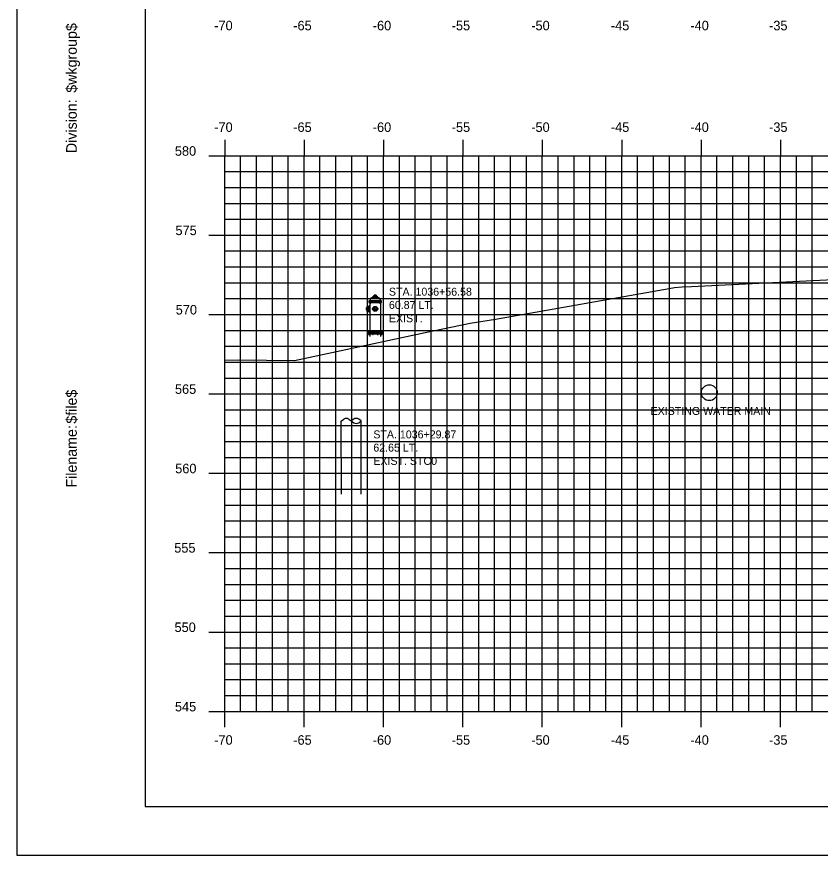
# Model space of a CAD drawing. Extents: x 1060559 to 1060729, y 779716 to 779826.
# Drawn here: x 1060559 to 1060609.6, y 779715.6 to 779768.5 of the extents above; entities that cross this region are included whole.
import ezdxf

# ---------------------------------------------------------------- set-up
doc = ezdxf.new("R2010")
doc.units = 0
for name, color, linetype in [('BORDER', 7, 'Continuous'), ('D_Text_Monospaced', 7, 'Continuous'), ('Existing Water Main', 7, 'Continuous'), ('H_V ANNOTATION', 7, 'Continuous'), ('M_Utilities_Hydrant', 7, 'Continuous'), ('MAJOR', 7, 'Continuous'), ('MINOR', 7, 'Continuous'), ('PLOT BOUNDARY', 7, 'Continuous'), ('S_Roadway_Centerline', 7, 'Continuous'), ('S_Utilities_Hydrant', 7, 'Continuous'), ('S_Utilities_Pole_Joint', 7, 'Continuous'), ('S_Utilities_Pole_Power', 7, 'Continuous')]:
    doc.layers.add(name, color=color, linetype=linetype)

msp = doc.modelspace()

# ---------------------------------------------------------------- linework, layer by layer
at = {"layer": 'BORDER'}
msp.add_lwpolyline([(1060567.08, 779718.706), (1060727.08, 779718.706), (1060727.08, 779823.706), (1060567.08, 779823.706)], close=True, dxfattribs=at)
at = {"layer": 'Existing Water Main'}
msp.add_circle((1060602.596, 779744.78), 0.501, dxfattribs=at)
at = {"layer": 'M_Utilities_Hydrant'}
for p, q in [((1060581.949, 779750.51), (1060581.16, 779750.51)), ((1060581.216, 779750.453), (1060581.216, 779748.647)), ((1060581.235, 779750.566), (1060581.235, 779750.583)), ((1060581.235, 779750.429), (1060581.235, 779750.453)), ((1060581.264, 779750.583), (1060581.264, 779750.566)), ((1060581.264, 779750.453), (1060581.264, 779750.429)), ((1060581.845, 779750.583), (1060581.845, 779750.566)), ((1060581.845, 779750.453), (1060581.845, 779750.429)), ((1060581.873, 779750.566), (1060581.873, 779750.583)), ((1060581.873, 779750.429), (1060581.873, 779750.453)), ((1060581.892, 779750.453), (1060581.892, 779748.647)), ((1060581.013, 779750.104), (1060581.013, 779750.014)), ((1060581.024, 779750.119), (1060581.024, 779749.998)), ((1060581.028, 779750.12), (1060581.028, 779749.998)), ((1060581.125, 779750.233), (1060581.125, 779749.884)), ((1060581.132, 779750.224), (1060581.125, 779750.224)), ((1060581.132, 779749.895), (1060581.125, 779749.895)), ((1060581.132, 779749.89), (1060581.132, 779750.228)), ((1060582.035, 779748.59), (1060581.084, 779748.59)), ((1060582.035, 779748.534), (1060581.084, 779748.534)), ((1060581.144, 779748.664), (1060581.144, 779748.647)), ((1060581.144, 779748.477), (1060581.144, 779748.453)), ((1060581.172, 779748.647), (1060581.172, 779748.664)), ((1060581.172, 779748.453), (1060581.172, 779748.477)), ((1060581.216, 779748.477), (1060581.216, 779748.311)), ((1060581.396, 779748.664), (1060581.396, 779748.647)), ((1060581.396, 779748.477), (1060581.396, 779748.453)), ((1060581.424, 779748.647), (1060581.424, 779748.664)), ((1060581.424, 779748.453), (1060581.424, 779748.477)), ((1060581.696, 779748.664), (1060581.696, 779748.647)), ((1060581.696, 779748.477), (1060581.696, 779748.453)), ((1060581.724, 779748.647), (1060581.724, 779748.664)), ((1060581.724, 779748.453), (1060581.724, 779748.477)), ((1060581.892, 779748.477), (1060581.892, 779748.311)), ((1060581.947, 779748.664), (1060581.947, 779748.647)), ((1060581.947, 779748.477), (1060581.947, 779748.453)), ((1060581.976, 779748.647), (1060581.976, 779748.664)), ((1060581.976, 779748.453), (1060581.976, 779748.477))]:
    msp.add_line(p, q, dxfattribs=at)
for points in [[(1060581.611, 779750.877), (1060581.611, 779750.933), (1060581.498, 779750.933), (1060581.498, 779750.877)], [(1060581.222, 779750.566), (1060581.222, 779750.583), (1060581.225, 779750.587), (1060581.274, 779750.587), (1060581.277, 779750.583), (1060581.277, 779750.566), (1060581.222, 779750.566)], [(1060581.277, 779750.453), (1060581.277, 779750.429), (1060581.274, 779750.425), (1060581.225, 779750.425), (1060581.222, 779750.429), (1060581.222, 779750.453), (1060581.277, 779750.453)], [(1060581.235, 779750.432), (1060581.235, 779750.416), (1060581.264, 779750.416), (1060581.264, 779750.429)], [(1060581.887, 779750.566), (1060581.887, 779750.583), (1060581.883, 779750.587), (1060581.835, 779750.587), (1060581.831, 779750.583), (1060581.831, 779750.566), (1060581.887, 779750.566)], [(1060581.831, 779750.453), (1060581.831, 779750.429), (1060581.835, 779750.425), (1060581.883, 779750.425), (1060581.887, 779750.429), (1060581.887, 779750.453), (1060581.831, 779750.453)], [(1060581.873, 779750.432), (1060581.873, 779750.416), (1060581.845, 779750.416), (1060581.845, 779750.429)], [(1060581.013, 779750.104), (1060580.978, 779750.104), (1060580.978, 779750.014), (1060581.013, 779750.014)], [(1060581.587, 779750.015), (1060581.522, 779750.015), (1060581.503, 779750.076), (1060581.554, 779750.114), (1060581.606, 779750.076), (1060581.587, 779750.015)], [(1060581.186, 779748.647), (1060581.186, 779748.664), (1060581.182, 779748.668), (1060581.134, 779748.668), (1060581.13, 779748.664), (1060581.13, 779748.647), (1060581.186, 779748.647)], [(1060581.13, 779748.477), (1060581.13, 779748.453), (1060581.134, 779748.45), (1060581.182, 779748.45), (1060581.186, 779748.453), (1060581.186, 779748.477), (1060581.13, 779748.477)], [(1060581.172, 779748.456), (1060581.172, 779748.44), (1060581.144, 779748.44), (1060581.144, 779748.453)], [(1060581.438, 779748.647), (1060581.438, 779748.664), (1060581.434, 779748.668), (1060581.385, 779748.668), (1060581.381, 779748.664), (1060581.381, 779748.647), (1060581.438, 779748.647)], [(1060581.381, 779748.477), (1060581.381, 779748.453), (1060581.385, 779748.45), (1060581.434, 779748.45), (1060581.438, 779748.453), (1060581.438, 779748.477), (1060581.381, 779748.477)], [(1060581.424, 779748.456), (1060581.424, 779748.44), (1060581.396, 779748.44), (1060581.396, 779748.453)], [(1060581.738, 779748.647), (1060581.738, 779748.664), (1060581.734, 779748.668), (1060581.686, 779748.668), (1060581.682, 779748.664), (1060581.682, 779748.647), (1060581.738, 779748.647)], [(1060581.682, 779748.477), (1060581.682, 779748.453), (1060581.686, 779748.45), (1060581.734, 779748.45), (1060581.738, 779748.453), (1060581.738, 779748.477), (1060581.682, 779748.477)], [(1060581.724, 779748.456), (1060581.724, 779748.44), (1060581.696, 779748.44), (1060581.696, 779748.453)], [(1060581.989, 779748.647), (1060581.989, 779748.664), (1060581.986, 779748.668), (1060581.937, 779748.668), (1060581.933, 779748.664), (1060581.933, 779748.647), (1060581.989, 779748.647)], [(1060581.933, 779748.477), (1060581.933, 779748.453), (1060581.937, 779748.45), (1060581.986, 779748.45), (1060581.989, 779748.453), (1060581.989, 779748.477), (1060581.933, 779748.477)], [(1060581.976, 779748.456), (1060581.976, 779748.44), (1060581.947, 779748.44), (1060581.947, 779748.453)]]:
    msp.add_lwpolyline(points, dxfattribs=at)
for radius in [0.158, 0.128]:
    msp.add_circle((1060581.554, 779750.059), radius, dxfattribs=at)
at = {"layer": 'MAJOR'}
for p, q in [((1060572.079, 779760.708), (1060572.079, 779759.706)), ((1060577.079, 779760.708), (1060577.079, 779759.706)), ((1060582.079, 779760.708), (1060582.079, 779759.706)), ((1060587.079, 779760.708), (1060587.079, 779759.706)), ((1060592.079, 779760.708), (1060592.079, 779759.706)), ((1060597.079, 779760.708), (1060597.079, 779759.706)), ((1060602.079, 779760.708), (1060602.079, 779759.706)), ((1060607.079, 779760.708), (1060607.079, 779759.706)), ((1060571.077, 779759.706), (1060572.079, 779759.706)), ((1060572.079, 779759.706), (1060712.079, 779759.706)), ((1060572.079, 779724.706), (1060572.079, 779759.706)), ((1060572.079, 779724.706), (1060572.079, 779759.706)), ((1060572.079, 779759.706), (1060712.079, 779759.706)), ((1060577.079, 779724.706), (1060577.079, 779759.706)), ((1060582.079, 779724.706), (1060582.079, 779759.706)), ((1060587.079, 779724.706), (1060587.079, 779759.706)), ((1060592.079, 779724.706), (1060592.079, 779759.706)), ((1060597.079, 779724.706), (1060597.079, 779759.706)), ((1060602.079, 779724.706), (1060602.079, 779759.706)), ((1060607.079, 779724.706), (1060607.079, 779759.706)), ((1060571.077, 779754.706), (1060572.079, 779754.706)), ((1060572.079, 779754.706), (1060712.079, 779754.706)), ((1060571.077, 779749.706), (1060572.079, 779749.706)), ((1060572.079, 779749.706), (1060712.079, 779749.706)), ((1060571.077, 779744.706), (1060572.079, 779744.706)), ((1060572.079, 779744.706), (1060712.079, 779744.706)), ((1060571.077, 779739.706), (1060572.079, 779739.706)), ((1060572.079, 779739.706), (1060712.079, 779739.706)), ((1060571.077, 779734.706), (1060572.079, 779734.706)), ((1060572.079, 779734.706), (1060712.079, 779734.706)), ((1060571.077, 779729.706), (1060572.079, 779729.706)), ((1060572.079, 779729.706), (1060712.079, 779729.706)), ((1060571.077, 779724.706), (1060572.079, 779724.706)), ((1060572.079, 779724.706), (1060712.079, 779724.706)), ((1060572.079, 779724.706), (1060712.079, 779724.706)), ((1060572.079, 779723.704), (1060572.079, 779724.706)), ((1060577.079, 779723.704), (1060577.079, 779724.706)), ((1060582.079, 779723.704), (1060582.079, 779724.706)), ((1060587.079, 779723.704), (1060587.079, 779724.706)), ((1060592.079, 779723.704), (1060592.079, 779724.706)), ((1060597.079, 779723.704), (1060597.079, 779724.706)), ((1060602.079, 779723.704), (1060602.079, 779724.706)), ((1060607.079, 779723.704), (1060607.079, 779724.706))]:
    msp.add_line(p, q, dxfattribs=at)
at = {"layer": 'MINOR'}
for p, q in [((1060573.079, 779724.706), (1060573.079, 779759.706)), ((1060574.079, 779724.706), (1060574.079, 779759.706)), ((1060575.079, 779724.706), (1060575.079, 779759.706)), ((1060576.079, 779724.706), (1060576.079, 779759.706)), ((1060578.079, 779724.706), (1060578.079, 779759.706)), ((1060579.079, 779724.706), (1060579.079, 779759.706)), ((1060580.079, 779724.706), (1060580.079, 779759.706)), ((1060581.079, 779724.706), (1060581.079, 779759.706)), ((1060583.079, 779724.706), (1060583.079, 779759.706)), ((1060584.079, 779724.706), (1060584.079, 779759.706)), ((1060585.079, 779724.706), (1060585.079, 779759.706)), ((1060586.079, 779724.706), (1060586.079, 779759.706)), ((1060588.079, 779724.706), (1060588.079, 779759.706)), ((1060589.079, 779724.706), (1060589.079, 779759.706)), ((1060590.079, 779724.706), (1060590.079, 779759.706)), ((1060591.079, 779724.706), (1060591.079, 779759.706)), ((1060593.079, 779724.706), (1060593.079, 779759.706)), ((1060594.079, 779724.706), (1060594.079, 779759.706)), ((1060595.079, 779724.706), (1060595.079, 779759.706)), ((1060596.079, 779724.706), (1060596.079, 779759.706)), ((1060598.079, 779724.706), (1060598.079, 779759.706)), ((1060599.079, 779724.706), (1060599.079, 779759.706)), ((1060600.079, 779724.706), (1060600.079, 779759.706)), ((1060601.079, 779724.706), (1060601.079, 779759.706)), ((1060603.079, 779724.706), (1060603.079, 779759.706)), ((1060604.079, 779724.706), (1060604.079, 779759.706)), ((1060605.079, 779724.706), (1060605.079, 779759.706)), ((1060606.079, 779724.706), (1060606.079, 779759.706)), ((1060608.079, 779724.706), (1060608.079, 779759.706)), ((1060609.079, 779724.706), (1060609.079, 779759.706)), ((1060572.079, 779758.706), (1060712.079, 779758.706)), ((1060572.079, 779758.706), (1060573.081, 779758.706)), ((1060572.079, 779757.706), (1060712.079, 779757.706)), ((1060572.079, 779757.706), (1060573.081, 779757.706)), ((1060572.079, 779756.706), (1060712.079, 779756.706)), ((1060572.079, 779756.706), (1060573.081, 779756.706)), ((1060572.079, 779755.706), (1060712.079, 779755.706)), ((1060572.079, 779755.706), (1060573.081, 779755.706)), ((1060572.079, 779753.706), (1060712.079, 779753.706)), ((1060572.079, 779753.706), (1060573.081, 779753.706)), ((1060572.079, 779752.706), (1060712.079, 779752.706)), ((1060572.079, 779752.706), (1060573.081, 779752.706)), ((1060572.079, 779751.706), (1060712.079, 779751.706)), ((1060572.079, 779751.706), (1060573.081, 779751.706)), ((1060572.079, 779750.706), (1060712.079, 779750.706)), ((1060572.079, 779750.706), (1060573.081, 779750.706)), ((1060572.079, 779748.706), (1060712.079, 779748.706)), ((1060572.079, 779748.706), (1060573.081, 779748.706)), ((1060572.079, 779747.706), (1060712.079, 779747.706)), ((1060572.079, 779747.706), (1060573.081, 779747.706)), ((1060572.079, 779746.706), (1060712.079, 779746.706)), ((1060572.079, 779746.706), (1060573.081, 779746.706)), ((1060572.079, 779745.706), (1060712.079, 779745.706)), ((1060572.079, 779745.706), (1060573.081, 779745.706)), ((1060572.079, 779743.706), (1060712.079, 779743.706)), ((1060572.079, 779743.706), (1060573.081, 779743.706)), ((1060572.079, 779742.706), (1060712.079, 779742.706)), ((1060572.079, 779742.706), (1060573.081, 779742.706)), ((1060572.079, 779741.706), (1060712.079, 779741.706)), ((1060572.079, 779741.706), (1060573.081, 779741.706)), ((1060572.079, 779740.706), (1060712.079, 779740.706)), ((1060572.079, 779740.706), (1060573.081, 779740.706)), ((1060572.079, 779738.706), (1060712.079, 779738.706)), ((1060572.079, 779738.706), (1060573.081, 779738.706)), ((1060572.079, 779737.706), (1060712.079, 779737.706)), ((1060572.079, 779737.706), (1060573.081, 779737.706)), ((1060572.079, 779736.706), (1060712.079, 779736.706)), ((1060572.079, 779736.706), (1060573.081, 779736.706)), ((1060572.079, 779735.706), (1060712.079, 779735.706)), ((1060572.079, 779735.706), (1060573.081, 779735.706)), ((1060572.079, 779733.706), (1060712.079, 779733.706)), ((1060572.079, 779733.706), (1060573.081, 779733.706)), ((1060572.079, 779732.706), (1060712.079, 779732.706)), ((1060572.079, 779732.706), (1060573.081, 779732.706)), ((1060572.079, 779731.706), (1060712.079, 779731.706)), ((1060572.079, 779731.706), (1060573.081, 779731.706)), ((1060572.079, 779730.706), (1060712.079, 779730.706)), ((1060572.079, 779730.706), (1060573.081, 779730.706)), ((1060572.079, 779728.706), (1060712.079, 779728.706)), ((1060572.079, 779728.706), (1060573.081, 779728.706)), ((1060572.079, 779727.706), (1060712.079, 779727.706)), ((1060572.079, 779727.706), (1060573.081, 779727.706)), ((1060572.079, 779726.706), (1060712.079, 779726.706)), ((1060572.079, 779726.706), (1060573.081, 779726.706)), ((1060572.079, 779725.706), (1060712.079, 779725.706)), ((1060572.079, 779725.706), (1060573.081, 779725.706))]:
    msp.add_line(p, q, dxfattribs=at)
at = {"layer": 'PLOT BOUNDARY'}
msp.add_lwpolyline([(1060558.986, 779715.646), (1060728.986, 779715.646), (1060728.986, 779825.646), (1060558.986, 779825.646)], close=True, dxfattribs=at)
at = {"layer": 'S_Roadway_Centerline'}
msp.add_lwpolyline([(1060572.079, 779746.823), (1060572.953, 779746.846), (1060576.475, 779746.799), (1060584.699, 779748.564), (1060587.544, 779749.165), (1060589.137, 779749.419), (1060600.06, 779751.353), (1060600.399, 779751.407), (1060600.894, 779751.457), (1060601.472, 779751.475), (1060617.199, 779752.241)], dxfattribs=at)
at = {"layer": 'S_Utilities_Hydrant'}
for p, q in [((1060581.401, 779750.821), (1060581.707, 779750.821)), ((1060581.441, 779750.862), (1060581.441, 779750.821)), ((1060581.65, 779750.878), (1060581.458, 779750.877)), ((1060581.667, 779750.821), (1060581.667, 779750.862)), ((1060581.16, 779750.55), (1060581.16, 779750.469)), ((1060581.932, 779750.566), (1060581.176, 779750.566)), ((1060581.255, 779750.694), (1060581.216, 779750.566)), ((1060581.216, 779750.295), (1060581.216, 779750.295)), ((1060581.554, 779750.765), (1060581.323, 779750.765)), ((1060581.554, 779750.765), (1060581.785, 779750.765)), ((1060581.854, 779750.694), (1060581.892, 779750.566)), ((1060581.013, 779750.107), (1060581.013, 779750.104)), ((1060581.013, 779750.012), (1060581.013, 779750.014)), ((1060581.048, 779750.126), (1060581.04, 779750.125)), ((1060581.048, 779749.991), (1060581.04, 779749.993)), ((1060581.048, 779749.901), (1060581.048, 779750.218)), ((1060581.125, 779749.884), (1060581.063, 779749.884)), ((1060581.064, 779750.233), (1060581.125, 779750.233)), ((1060581.216, 779749.823), (1060581.216, 779749.823)), ((1060581.109, 779748.647), (1060582.01, 779748.647)), ((1060582.01, 779748.477), (1060581.109, 779748.477))]:
    msp.add_line(p, q, dxfattribs=at)
for points in [[(1060581.385, 779750.765), (1060581.385, 779750.806), (1060581.386, 779750.806), (1060581.385, 779750.806)], [(1060581.723, 779750.806), (1060581.722, 779750.806), (1060581.723, 779750.806), (1060581.723, 779750.765)], [(1060581.175, 779750.453), (1060581.175, 779750.453), (1060581.933, 779750.453), (1060581.933, 779750.453)], [(1060581.949, 779750.469), (1060581.949, 779750.55), (1060581.949, 779750.55)]]:
    msp.add_lwpolyline(points, dxfattribs=at)
for centre, radius, start, end in [((1060581.404, 779750.802), 0.0191, 96.9921, 168.8028), ((1060581.46, 779750.858), 0.019, 96.6009, 168.4116), ((1060581.648, 779750.859), 0.0191, 11.1972, 83.0079), ((1060581.705, 779750.802), 0.019, 11.5319, 83.3426), ((1060581.118, 779750.332), 0.105, 277.4234, 339.5299), ((1060581.179, 779750.547), 0.0191, 96.9921, 168.8028), ((1060581.179, 779750.471), 0.0191, 186.9921, 258.8028), ((1060581.228, 779750.579), 0.00826, 32.9144, 129.4939), ((1060581.228, 779750.433), 0.00826, 230.5064, 327.0859), ((1060581.25, 779750.559), 0.0282, 60.0007, 120.0007), ((1060581.25, 779750.453), 0.0282, 240.0007, 300.0007), ((1060581.347, 779750.673), 0.0943, 104.4243, 167.4801), ((1060581.271, 779750.579), 0.00826, 50.5064, 147.0859), ((1060581.271, 779750.433), 0.00826, 212.9144, 309.4939), ((1060581.762, 779750.673), 0.0943, 12.5199, 75.5757), ((1060581.838, 779750.579), 0.00826, 32.9141, 129.4936), ((1060581.838, 779750.433), 0.00826, 230.5061, 327.0856), ((1060581.859, 779750.559), 0.0282, 59.9993, 119.9993), ((1060581.859, 779750.453), 0.0282, 239.9993, 299.9993), ((1060581.88, 779750.579), 0.00826, 50.5061, 147.0856), ((1060581.88, 779750.433), 0.00826, 212.9141, 309.4936), ((1060581.93, 779750.547), 0.0191, 11.1972, 83.0079), ((1060581.929, 779750.471), 0.0191, 281.1972, 353.0079), ((1060581.016, 779750.116), 0.00229, 150.6422, 170.5377), ((1060581.09, 779750.104), 0.0782, 170.5377, 171.4341), ((1060581.022, 779750.114), 0.00865, 171.4341, 174.1282), ((1060581.026, 779750.114), 0.013, 174.1282, 177.7182), ((1060581.141, 779750.109), 0.128, 177.7182, 178.8593), ((1060581.099, 779750.11), 0.0857, 178.8593, 179.715), ((1060581.785, 779750.107), 0.772, 179.715, 180), ((1060581.785, 779750.011), 0.772, 180, 180.285), ((1060581.099, 779750.008), 0.0857, 180.285, 181.1407), ((1060581.141, 779750.009), 0.128, 181.1407, 182.2818), ((1060581.026, 779750.004), 0.013, 182.2818, 185.8718), ((1060581.022, 779750.004), 0.00865, 185.8718, 188.5659), ((1060581.09, 779750.014), 0.0782, 188.5659, 189.4623), ((1060581.016, 779750.002), 0.00229, 189.4623, 209.3578), ((1060581.023, 779750.112), 0.0104, 141.3402, 150.6422), ((1060581.023, 779750.006), 0.0104, 209.3578, 218.6598), ((1060580.972, 779750.153), 0.055, 321.3402, 323.1301), ((1060580.972, 779749.965), 0.055, 36.8699, 38.6598), ((1060581.017, 779750.12), 0.000947, 97.125, 146.3099), ((1060581.002, 779750.131), 0.0174, 323.1301, 326.3099), ((1060581.002, 779749.987), 0.0174, 33.6901, 36.8699), ((1060581.017, 779749.998), 0.000947, 213.6901, 262.875), ((1060581.017, 779750.118), 0.00335, 71.565, 97.125), ((1060581.017, 779750), 0.00335, 262.875, 288.435), ((1060581.009, 779750.094), 0.0288, 68.1986, 71.5651), ((1060581.009, 779750.024), 0.0288, 288.4349, 291.8014), ((1060581.014, 779750.107), 0.0144, 63.435, 68.1986), ((1060581.014, 779750.011), 0.0144, 291.8014, 296.565), ((1060581.025, 779750.128), 0.0084, 243.4349, 251.565), ((1060581.025, 779749.99), 0.0084, 108.4349, 116.5651), ((1060581.025, 779750.13), 0.0109, 251.565, 258.6901), ((1060581.025, 779749.988), 0.0109, 101.3099, 108.4349), ((1060581.025, 779750.126), 0.00686, 258.6901, 270), ((1060581.025, 779749.992), 0.00686, 90, 101.3099), ((1060581.025, 779750.137), 0.0173, 270, 277.125), ((1060581.025, 779749.981), 0.0173, 82.875, 90), ((1060581.026, 779750.126), 0.00682, 277.125, 294.444), ((1060581.026, 779749.992), 0.00682, 65.556, 82.875), ((1060581.028, 779750.122), 0.00252, 294.444, 323.1301), ((1060581.028, 779749.996), 0.00252, 36.8699, 65.556), ((1060581.037, 779750.115), 0.00939, 135, 143.1301), ((1060581.037, 779750.003), 0.00939, 216.8699, 225), ((1060581.037, 779750.115), 0.00939, 126.8699, 135), ((1060581.037, 779750.003), 0.00939, 225, 233.1301), ((1060581.034, 779750.12), 0.00357, 105.7372, 126.8699), ((1060581.034, 779749.998), 0.00357, 233.1301, 254.2628), ((1060581.065, 779750.011), 0.117, 102.0619, 105.7372), ((1060581.065, 779750.107), 0.117, 254.2628, 257.9381), ((1060581.066, 779750.214), 0.0191, 96.9921, 168.8028), ((1060581.067, 779749.903), 0.0192, 186.7328, 258.5435), ((1060581.118, 779749.786), 0.105, 20.4701, 82.5766), ((1060581.222, 779748.562), 0.141, 143.1301, 216.8699), ((1060581.137, 779748.66), 0.00826, 32.9141, 129.4936), ((1060581.137, 779748.458), 0.00826, 230.5061, 327.0856), ((1060581.158, 779748.64), 0.0282, 59.9993, 119.9993), ((1060581.158, 779748.478), 0.0282, 239.9993, 299.9993), ((1060581.179, 779748.66), 0.00826, 50.5061, 147.0856), ((1060581.179, 779748.458), 0.00826, 212.9141, 309.4936), ((1060581.389, 779748.66), 0.00826, 32.9141, 129.4936), ((1060581.389, 779748.458), 0.00826, 230.5061, 327.0856), ((1060581.41, 779748.64), 0.0282, 59.9993, 119.9993), ((1060581.41, 779748.478), 0.0282, 239.9993, 299.9993), ((1060581.431, 779748.66), 0.00826, 50.5061, 147.0856), ((1060581.431, 779748.458), 0.00826, 212.9141, 309.4936), ((1060581.689, 779748.66), 0.00826, 32.9141, 129.4936), ((1060581.689, 779748.458), 0.00826, 230.5061, 327.0856), ((1060581.71, 779748.64), 0.0282, 59.9993, 119.9993), ((1060581.71, 779748.478), 0.0282, 239.9993, 299.9993), ((1060581.731, 779748.66), 0.00826, 50.5061, 147.0856), ((1060581.731, 779748.458), 0.00826, 212.9141, 309.4936), ((1060581.94, 779748.66), 0.00826, 32.9141, 129.4936), ((1060581.94, 779748.458), 0.00826, 230.5061, 327.0856), ((1060581.961, 779748.64), 0.0282, 59.9993, 119.9993), ((1060581.961, 779748.478), 0.0282, 239.9993, 299.9993), ((1060581.982, 779748.66), 0.00826, 50.5061, 147.0856), ((1060581.982, 779748.458), 0.00826, 212.9141, 309.4936), ((1060581.898, 779748.562), 0.141, 323.1301, 36.8699)]:
    msp.add_arc(centre, radius, start, end, dxfattribs=at)
at = {"layer": 'S_Utilities_Pole_Joint'}
for p, q in [((1060579.425, 779743.003), (1060579.581, 779743.113)), ((1060579.894, 779743.113), (1060580.05, 779743.003)), ((1060580.207, 779743.113), (1060580.05, 779743.003)), ((1060580.05, 779743.003), (1060580.207, 779742.892)), ((1060580.675, 779743.003), (1060580.519, 779743.113)), ((1060580.519, 779742.892), (1060580.675, 779743.003))]:
    msp.add_line(p, q, dxfattribs=at)
for centre, start, end in [((1060579.738, 779742.892), 90, 125.2644), ((1060579.738, 779742.892), 54.7356, 90), ((1060580.363, 779742.892), 90, 125.2644), ((1060580.363, 779743.113), 234.7356, 270), ((1060580.363, 779742.892), 54.7356, 90), ((1060580.363, 779743.113), 270, 305.2644)]:
    msp.add_arc(centre, 0.271, start, end, dxfattribs=at)
at = {"layer": 'S_Utilities_Pole_Power'}
for p, q in [((1060579.425, 779738.383), (1060579.422, 779743.003)), ((1060580.675, 779738.383), (1060580.672, 779743.003))]:
    msp.add_line(p, q, dxfattribs=at)

# ---------------------------------------------------------------- texts
at = {"layer": 'BORDER'}
for s, p in [('$wkgroup$', (1060562.765, 779763.675)), ('Division:', (1060562.765, 779759.872)), ('$file$', (1060562.765, 779742.831)), ('Filename:', (1060562.765, 779738.804))]:
    msp.add_text(s, height=0.6696, rotation=90, dxfattribs=at).set_placement(p)
at = {"layer": 'D_Text_Monospaced'}
for s, height, p in [('STA. 1036+56.58', 0.49998, (1060582.421, 779750.891)), ('60.87 LT.', 0.5, (1060582.421, 779750.057)), ('EXIST. ', 0.5, (1060582.421, 779749.217)), ('EXISTING WATER MAIN', 0.49998, (1060598.896, 779743.38)), ('STA. 1036+29.87', 0.49998, (1060581.439, 779741.904)), ('62.65 LT.', 0.5, (1060581.439, 779741.07)), ('EXIST. STC0', 0.49998, (1060581.439, 779740.23))]:
    msp.add_text(s, height=height, dxfattribs=at).set_placement(p)
at = {"layer": 'H_V ANNOTATION'}
for s, p in [('-70', (1060571.421, 779767.606)), ('-65', (1060576.397, 779767.606)), ('-60', (1060581.405, 779767.606)), ('-50', (1060591.384, 779767.606)), ('-40', (1060601.405, 779767.606)), ('-35', (1060606.36, 779767.606)), ('-55', (1060586.376, 779767.606)), ('-45', (1060596.397, 779767.606)), ('-70', (1060571.421, 779761.206)), ('-65', (1060576.397, 779761.206)), ('-60', (1060581.405, 779761.206)), ('-55', (1060586.376, 779761.206)), ('-50', (1060591.384, 779761.206)), ('-45', (1060596.397, 779761.206)), ('-40', (1060601.405, 779761.206)), ('-35', (1060606.36, 779761.206)), ('580', (1060568.941, 779759.706)), ('575', (1060568.979, 779754.706)), ('570', (1060568.995, 779749.706)), ('565', (1060568.947, 779744.706)), ('560', (1060568.963, 779739.706)), ('555', (1060568.904, 779734.706)), ('550', (1060568.92, 779729.706)), ('545', (1060568.947, 779724.706)), ('-70', (1060571.421, 779722.606)), ('-65', (1060576.397, 779722.606)), ('-60', (1060581.405, 779722.606)), ('-55', (1060586.376, 779722.606)), ('-50', (1060591.384, 779722.606)), ('-45', (1060596.397, 779722.606)), ('-40', (1060601.405, 779722.606)), ('-35', (1060606.36, 779722.606))]:
    msp.add_text(s, height=0.6, dxfattribs=at).set_placement(p)
at = {"layer": 'MAJOR'}
msp.add_text('-', height=0.006, dxfattribs=at).set_placement((1060572.075, 779724.706))

doc.saveas('drawing.dxf')
